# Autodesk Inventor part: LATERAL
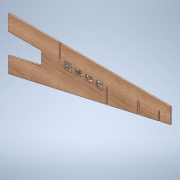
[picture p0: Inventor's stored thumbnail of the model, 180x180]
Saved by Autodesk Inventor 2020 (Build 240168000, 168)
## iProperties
Part Number: LATERAL
Material: Madera (abedul)
Document SubType Name: Modeling
Designer: Arias
Mass: 0.170564 g
Surface Area: 12.6786 cm^2
Volume: 0.110684 cm^3
Density: 0.55 g/cm^3
Appearance: Abedul - Natural pulido
Author: Arias
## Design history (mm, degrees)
sketch "Boceto4"
  geometry: L1 (0, 0)-(-2440, 0); L2 (-2440, 0)-(-2440, -1220); L3 (-2440, -1220)-(0, -1220); L4 (0, -1220)-(0, 0); L5 (-42.072, -54.378)-(-42.072, -204.378); L6 (-42.072, -204.378)-(-357.424, -204.378); L7 (-42.072, -554.378)-(-42.072, -404.378); L8 (-1592.072, -54.378)-(-1592.072, -201.619); L9 (-42.072, -404.378)-(-357.424, -332.608); L10 (-1492.072, -139.378)-(-1492.072, -224.378); L11 (-1292.072, -162.136)-(-1292.072, -269.895); L12 (-992.072, -196.274)-(-992.072, -338.171); L13 (-357.424, -204.378)-(-357.424, -332.608); L14 (-542.072, -54.378)-(-542.072, -176.378); L15 (-1480.972, -226.904)-(-1480.972, -139.378); L16 (-1492.072, -139.378)-(-1480.972, -139.378); L17 (-1280.972, -272.421)-(-1280.972, -162.136); L18 (-980.972, -340.697)-(-980.972, -196.274); L19 (-1292.072, -162.136)-(-1280.972, -162.136); L20 (-992.072, -196.274)-(-980.972, -196.274); L21 (-530.972, -54.378)-(-530.972, -176.378); L22 (-542.072, -176.378)-(-530.972, -176.378); L23 (-980.972, -340.697)-(-42.072, -554.378); L24 (-1280.972, -272.421)-(-992.072, -338.171); L25 (-1592.072, -201.619)-(-1492.072, -224.378); L26 (-1480.972, -226.904)-(-1292.072, -269.895); L27 (-42.072, -54.378)-(-530.972, -54.378); L28 (-542.072, -54.378)-(-1592.072, -54.378)
  constraints: 56 end point, 8 vertical, 7 parallel, 6 horizontal, 3 perpendicular
  dimensions: "d11" = 2440 distance of L3.end L2.end; "d12" = 1220 distance of L2.end L1.end; "d14" = 1550 distance of L5.start L8.start; "d15" = 150 distance of L5.start L5.end; "d17" = 500 distance of L5.start L7.start; "d18" = 150 distance of L7.start L7.end; "d22" = 100 distance from line of L8 L10.start; "d26" = 11.1 distance between parallel lines of L15 L10; "d27" = 11.1 distance between parallel lines of L11 L17; "d28" = 11.1 distance between parallel lines of L12 L18; "d29" = 11.1 distance between parallel lines of L21 L14; "d33" = 122 distance of L14.start L14.end
extrude "Extrusión2" new body sketch "Boceto4" distance "d31" = 11.1; taper "d32" = 0 deg
sketch "Boceto5"
  geometry: L1 (587.737, 318.671)-(945.058, 318.671); L2 (945.058, 318.671)-(945.058, 90.671); L3 (945.058, 90.671)-(587.737, 90.671); L4 (587.737, 90.671)-(587.737, 318.671); L5 (942.703, 215.496)-(942.703, 203.059); L6 (942.703, 203.059)-(939.066, 203.059); L7 (939.066, 203.059)-(939.066, 215.496); L8 (939.066, 215.496)-(942.703, 215.496); L9 (542.072, 54.378)-(1592.072, 54.378) reference; 1 further point
  constraints: 4 other
extrude "Extrusión3" cut sketch "Boceto5" distance "d35" = 12; taper "d36" = 0 deg
node "Sólido2"
other parameters: "sa_0" = 140000, "sa_1" = 0, "sa_2" = 0, "sa_3" = -2000000, "d21" = 90 deg, "d30" = 245
